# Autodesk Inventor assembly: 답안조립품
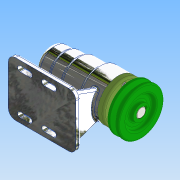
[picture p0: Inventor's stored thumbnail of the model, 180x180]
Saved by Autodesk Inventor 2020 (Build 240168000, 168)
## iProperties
Created: 2021-10
Part Number: 답안조립품
Document SubType Name: Assembly
Designer: user
Author: user
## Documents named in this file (12)
- C:\Users\user\Desktop\711007V1006\답안조립품.iam
- C:\Users\user\Desktop\711007V1006\V벨트풀리.ipt
- C:\Users\user\Desktop\711007V1006\멈춤나사 M3.ipt
- C:\Users\user\Desktop\711007V1006\베어링 6004.ipt
- C:\Users\user\Desktop\711007V1006\베어링 51202.ipt
- C:\Users\user\Desktop\711007V1006\본체.ipt
- C:\Users\user\Desktop\711007V1006\볼트 M4.ipt
- C:\Users\user\Desktop\711007V1006\어댑터슬리브.ipt
- C:\Users\user\Desktop\711007V1006\오일 실 20x35x7.ipt
- C:\Users\user\Desktop\711007V1006\축.ipt
- C:\Users\user\Desktop\711007V1006\커버.ipt
- C:\Users\user\Desktop\711007V1006\키 5x5.ipt
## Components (1 placed, 1 different names)
1. V벨트풀리:1
